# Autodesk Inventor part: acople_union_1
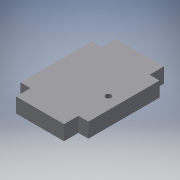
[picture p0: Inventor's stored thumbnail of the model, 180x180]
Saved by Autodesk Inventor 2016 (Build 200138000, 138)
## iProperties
Created: 2017-06
Part Number: acople_union_1
Material: Generic
Document SubType Name: Modeling
Designer: laboratorioesan
Density: 1 g/cm^3
Appearance: Default
Author: laboratorioesan
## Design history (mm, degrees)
sketch "Sketch1"
  geometry: L1 (0, 0)-(-60, 0) reference; L2 (0, 0)-(0, 18.5) reference; L3 (-60, 18.5)-(0, 18.5) reference; L4 (-60, 0)-(-60, 18.5) reference; L5 (-60, 18.5)-(0, 18.5); L6 (0, 18.5)-(0, 0.5); L7 (0, 0.5)-(-60, 0.5); L8 (-60, 0.5)-(-60, 18.5); L9 (-72.5, 18.5)-(12.5, 18.5) reference; L10 (-72.5, 18.5)-(12.5, 18.5); L11 (12.5, 18.5)-(12.5, 107.5); L12 (12.5, 107.5)-(-72.5, 107.5); L13 (-72.5, 107.5)-(-72.5, 18.5); L14 (-60, 107.5)-(0, 107.5); L15 (0, 107.5)-(0, 125.5); L16 (0, 125.5)-(-60, 125.5); L17 (-60, 125.5)-(-60, 107.5)
  constraints: 24 end point, 6 parallel, 3 horizontal, 3 perpendicular, 2 point on line
  dimensions: "d0" = 18 distance of L5.end L6.end; "d1" = 89 distance of L11.end L10.end; "d2" = 18 distance of L15.end L14.end
extrude "Extrusion1" new body sketch "Sketch1" distance "d3" = 18.5; taper "d4" = 0 deg
sketch "Sketch2"
  geometry: L1 (60, 125.5)-(60, 107.5) reference; L2 (0, 125.5)-(60, 125.5) reference; L3 (0, 107.5)-(0, 125.5) reference; L4 (-12.5, 107.5)-(0, 107.5) reference; L5 (-12.5, 18.5)-(-12.5, 107.5) reference; L6 (0, 18.5)-(-12.5, 18.5) reference; L7 (0, 0.5)-(0, 18.5) reference; L8 (60, 0.5)-(0, 0.5) reference; L9 (60, 18.5)-(60, 0.5) reference; L10 (72.5, 18.5)-(60, 18.5) reference; L11 (72.5, 107.5)-(72.5, 18.5) reference; L12 (60, 107.5)-(72.5, 107.5) reference; L13 (101.528, 33.5)-(-101.016, 33.5) reference; C1 r 3.5 at (2.5, 58.5); 1 further point
  constraints: 1 centre point
  dimensions: "d5" = 7 diameter of C1; "d6" = 15 distance from line of L5 C1.centre; "d7" = 25 distance from line of L13 C1.centre
extrude "Extrusion2" cut sketch "Sketch2" distance "d8" = 18.5; taper "d9" = 0 deg
body "Solid1"
node "Reference1"
node "Reference2"
node "Projected Loop1"
node "Reference3"
